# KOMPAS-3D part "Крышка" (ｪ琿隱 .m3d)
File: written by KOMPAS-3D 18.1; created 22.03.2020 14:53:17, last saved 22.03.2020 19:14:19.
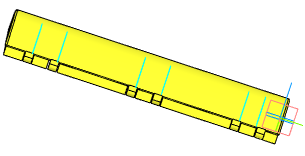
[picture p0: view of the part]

Document properties: Автор: windwican@hotmail.com; Полное имя файла: C:\Users\windw\Desktop\shkatilka1\bez petli\Измененная\крышка.m3d

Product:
- Part/product: Крышка
    Материал: Полиамид П-12Б-20  ТУ 6-05-898-73 (density 1020 kg/m3)
    Масса: 0.634773
  - Body: Тело 2
      Масса: 4.88899
  - Body: Тело 3
      Масса: 4.88899
  - Body: Тело 4
      Масса: 4.88899
  - Body: Тело 5
      Масса: 4.88899
  - Body: Тело 6
      Масса: 4.88899
  - Body: Тело 7
      Масса: 4.88899
  - Body: Тело 8
      Масса: 4.88899
  - Body: Тело 9
      Масса: 4.88899
  - Body: Тело 10
      Масса: 4.88899

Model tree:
1. Эскиз:1
2. Элемент выдавливания:2
     Расстояние 1 = 5
3. Эскиз:2  (with: Элемент выдавливания:2)
4. Элемент выдавливания:3
     Толщина стенки 1 = 3; Расстояние 1 = 499
5. Эскиз:3  (with: Элемент выдавливания:3)
6. Элемент выдавливания:4
     Расстояние 2 = 5
7. Эскиз:4  (with: Элемент выдавливания:2, Элемент выдавливания:4)
8. Элемент выдавливания:9
     Расстояние 1 = 10
9. Скругление:1  (with: Элемент выдавливания:3)
     Радиус = 4
10. Скругление:2  (with: Элемент выдавливания:4)
     Радиус = 3
11. Эскиз:5  (with: Элемент выдавливания:2)
12. Элемент выдавливания:10
     Расстояние 1 = 5
13. Элемент выдавливания:11  (with: Элемент выдавливания:10)
     Расстояние 1 = 7
14. Элемент выдавливания:12  (with: Элемент выдавливания:10)
     Расстояние 1 = 2.29502
15. Элемент выдавливания:13  (with: Элемент выдавливания:12)
     Расстояние 1 = 2
16. Скругление:3  (with: Элемент выдавливания:11)
     Радиус = 5
17. Скругление:4  (with: Элемент выдавливания:4)
     Радиус = 3
18. Скругление:5  (with: Элемент выдавливания:2)
     Радиус = 3
19. Эскиз:6  (with: Элемент выдавливания:2)
20. Элемент выдавливания:14
     Расстояние 2 = 505
21. Смещенная плоскость:1
     Расстояние = 35
22. Элемент выдавливания:15  (with: Элемент выдавливания:10)
     Расстояние 1 = 4
23. Скругление:6  (with: Элемент выдавливания:2)
     Радиус = 1
24. Эскиз:7  (with: Скругление:6)
25. Элемент выдавливания:16
     Толщина стенки 1 = 4; Расстояние 1 = 15
26. Скругление:7  (with: Элемент выдавливания:15)
     Радиус = 20
27. Смещенная плоскость:2
     Расстояние = 30.7
28. Эскиз:8
29. Элемент выдавливания:17
     Толщина стенки 1 = 4; Расстояние 2 = 15
30. Смещенная плоскость:3
     Расстояние = 144
31. Эскиз:9
32. Элемент выдавливания:18
     Толщина стенки 1 = 4; Расстояние 2 = 15
33. Смещенная плоскость:4
     Расстояние = 46.3
34. Эскиз:10
35. Элемент выдавливания:19
     Толщина стенки 1 = 4; Расстояние 2 = 15
36. Смещенная плоскость:5
     Расстояние = 144
37. Эскиз:11
38. Элемент выдавливания:20
     Толщина стенки 1 = 4; Расстояние 1 = 15
39. Смещенная плоскость:6
     Расстояние = 46
40. Эскиз:12
41. Элемент выдавливания:21
     Толщина стенки 1 = 4; Расстояние 2 = 15
42. Эскиз:13  (with: Элемент выдавливания:16, Скругление:5)
43. Элемент выдавливания:22
     Расстояние 2 = 15
44. Эскиз:14  (with: Элемент выдавливания:17)
45. Элемент выдавливания:23
     Расстояние 2 = 15
46. Эскиз:15  (with: Элемент выдавливания:18)
47. Элемент выдавливания:24
     Расстояние 2 = 15
48. Эскиз:16  (with: Элемент выдавливания:19)
49. Элемент выдавливания:25
     Расстояние 2 = 15
50. Эскиз:17  (with: Элемент выдавливания:20)
51. Элемент выдавливания:26
     Расстояние 2 = 15
52. Эскиз:18  (with: Элемент выдавливания:21)
53. Элемент выдавливания:27
     Расстояние 2 = 15
54. Эскиз:19  (with: Элемент выдавливания:2, Элемент выдавливания:3)
55. Элемент выдавливания:28
     Расстояние 1 = 497
56. Эскиз:20  (with: Элемент выдавливания:2, Элемент выдавливания:22, Скругление:5)
57. Элемент выдавливания:29
     Толщина стенки 1 = 1.2; Расстояние 2 = 504
58. Скругление:8  (with: Элемент выдавливания:29)
     Радиус = 3
59. Скругление:9  (with: Элемент выдавливания:29)
     Радиус = 3
60. Эскиз:21  (with: Элемент выдавливания:4)
61. Элемент выдавливания:30
     Расстояние 1 = 497
62. Эскиз:22  (with: Элемент выдавливания:4, Элемент выдавливания:22)
63. Элемент выдавливания:31
     Толщина стенки 1 = 2; Расстояние 1 = 16.4136
64. Эскиз:23  (with: Элемент выдавливания:31, Скругление:6)
65. Элемент выдавливания:32
     Толщина стенки 1 = 0.2; Расстояние 2 = 284.38
66. Эскиз:24  (with: Элемент выдавливания:31)
67. Элемент выдавливания:33  (labels: Полиамид П-12Б-20  ТУ 6-05-898-73)
     Толщина стенки 1 = 0.2; Расстояние 2 = 502.98

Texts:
  Точка начала. Х
  Точка начала. Y
  Точка начала. Z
